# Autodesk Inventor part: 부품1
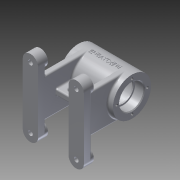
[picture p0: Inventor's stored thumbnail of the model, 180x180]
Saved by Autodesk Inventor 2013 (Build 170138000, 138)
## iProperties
Created: 2015-11
Part Number: 부품1
Material: 알루미늄 6061
Document SubType Name: Modeling
Designer: default
Density: 2.40731 g/cm^3
Mass: 318.572 g
Surface Area: 460.303 cm^2
Volume: 132.335 cm^3
Author: default
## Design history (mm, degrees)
sketch "스케치1"
  geometry: C1 r 25 at (0, 0); 1 further point
  constraints: 1 centre point, 1 coincident
  dimensions: "d0" = 50 diameter of C1
extrude "돌출1" new body sketch "스케치1" distance "d2" = 70; taper "d3" = 0 deg
node "작업 평면1"
sketch "스케치2"
  geometry: L1 (0, 25)-(70, 25) reference; L2 (70, -25)-(70, 25) reference; L3 (0, 25)-(0, -25) reference; L4 (0, -25)-(70, -25) reference; L5 (15, -6.491)-(55, -6.491); L6 (55, -6.491)-(55, -45); L7 (55, -45)-(15, -45); L8 (15, -45)-(15, -6.491); 3 further points
  constraints: 8 end point, 2 midpoint, 2 parallel, 1 horizontal, 1 perpendicular, 1 vertical alignment
  dimensions: "d5" = 20 distance between parallel lines of L4 L7; "d6" = 40 distance of L5.start L5.end
extrude "돌출2" join sketch "스케치2" stored distance "d7" = 8; taper "d8" = 0 deg
sketch "스케치3"
  geometry: L1 (-21, 45)-(29, 45); L2 (29, 45)-(29, -23); L3 (29, -23)-(-21, -23); L4 (-21, -23)-(-21, 45); C1 r 25 at (4, 45) reference; A1 r 25 centre (4, 45) between (0, 20.322) and (8, 20.322) reference; 1 further point
  constraints: 8 end point, 2 midpoint, 2 parallel, 1 coincident, 1 horizontal, 1 perpendicular
  dimensions: "d9" = 68 distance from line of A1.centre L3; "d10" = 50 distance of L1.start L1.end
extrude "돌출3" join sketch "스케치3" distance "d11" = 8; taper "d12" = 0 deg
sketch "스케치4"
  geometry: L1 (0, 0)-(0, 50) reference; L2 (8, 50)-(8, 0) reference; L3 (0, 50)-(8, 50) reference; L4 (20, -15)-(20, 65); L5 (0, 65)-(0, -15); A1 r 10 centre (10, 65) between (20, 65) and (0, 65); A2 r 10 centre (10, -15) between (0, -15) and (20, -15); 4 further points
  constraints: 4 end point, 4 midpoint, 4 point on circle, 4 tangent, 2 centre point, 1 horizontal alignment, 1 parallel, 1 perpendicular
  dimensions: "d13" = 20 distance between parallel lines of L5 L4; "d15" = 80 distance of A2.centre A1.centre
extrude "돌출4" join sketch "스케치4" distance "d16" = 10; taper "d17" = 0 deg
sketch "스케치5"
  geometry: C1 r 10 at (10, 15); C2 r 10 at (10, -65); A1 r 10 centre (10, -65) between (0, -65) and (20, -65) reference; A2 r 10 centre (10, 15) between (20, 15) and (0, 15) reference; 1 further point
  constraints: 2 centre point, 2 coincident, 2 concentric
extrude "돌출5" join sketch "스케치5" distance "d18" = 3; taper "d19" = 0 deg
sketch "스케치6"
  geometry: C1 r 10 at (0, 0) reference; C2 r 10 at (0, 80) reference; 3 further points
  constraints: 2 coincident
hole "구멍1" sketch "스케치6" at (0, 80), (0, 0) diameter "d20" = 6; stored, may be unused: countersink angle "d24" = 90 deg, drill point angle "d26" = 118 deg; dims "d21" = 6, "d22" = 12, "d23" = 4, "d25" = 8
node "작업 평면2"
sketch "스케치7"
  geometry: L1 (-55, -24.678)-(-15, -24.678) reference; L2 (-15, -45)-(-15, -24.678) reference; L3 (-27, -31.5)-(-43, -31.5); L4 (-43, -38.5)-(-27, -38.5); L5 (5, -68)-(-15, -68) reference; A1 r 3.5 centre (-43, -35) between (-43, -31.5) and (-43, -38.5); A2 r 3.5 centre (-27, -35) between (-27, -38.5) and (-27, -31.5); 3 further points
  constraints: 4 end point, 4 point on circle, 4 tangent, 2 centre point, 2 midpoint, 1 parallel, 1 perpendicular, 1 vertical alignment
  dimensions: "d27" = 3.5 radius of A1; "d29" = 16 distance of A2.centre A1.centre; "d30" = 33 distance from line of L5 A2.centre
extrude "돌출6" cut sketch "스케치7" stored distance "d31" = 3; taper "d32" = 0 deg
node "작업 평면3"
sketch "스케치8"
  geometry: L1 (0, 25)-(-70, 25) reference; L2 (0, -25)-(0, 25) reference; C1 r 5 at (-35, 0); 3 further points
  constraints: 2 midpoint, 1 centre point, 1 horizontal alignment, 1 vertical alignment
  dimensions: "d34" = 10 diameter of C1
extrude "돌출7" join sketch "스케치8" distance "d36" = 28; taper "d37" = 0 deg
sketch "스케치9"
  geometry: L1 (0, 0)-(0, -21.987); L2 (0, 0)-(14, -24.249); L3 (19.196, -21.249)-(6.746, 0.316); L4 (14, -24.249)-(19.196, -21.249); L5 (6.746, 0.316)-(1.808, -3.131); C1 r 25 at (0, 0) reference; 1 further point
  constraints: 10 end point, 1 parallel, 1 perpendicular, 1 point on line, 1 vertical
  dimensions: "d38" = 30 deg angle of L2 L1; "d39" = 6 distance between parallel lines of L3 L2; "d41" = 28 distance from line of L4 point (0, 0)
revolve "회전1" sketch "스케치9" stored, may be unused: angle "d42" = 90 deg
sketch "스케치10"
  geometry: C1 r 25 at (0, 0) reference; C2 r 16 at (0, 0)
  constraints: 1 centre point, 1 coincident
  dimensions: "d43" = 32 diameter of C2
extrude "돌출8" cut sketch "스케치10" distance "d45" = 12; taper "d46" = 0 deg
sketch "스케치11"
  geometry: C1 r 16 at (0, 0) reference; C2 r 14 at (0, 0)
  constraints: 1 centre point, 1 coincident
  dimensions: "d47" = 28 diameter of C2
extrude "돌출9" cut sketch "스케치11" distance "d49" = 2; taper "d50" = 0 deg
sketch "스케치12"
  geometry: C1 r 25 at (0, 0) reference; C2 r 16 at (0, 0)
  constraints: 1 centre point, 1 coincident
  dimensions: "d51" = 32 diameter of C2
extrude "돌출10" cut sketch "스케치12" distance "d53" = 12; taper "d54" = 0 deg
sketch "스케치13"
  geometry: C1 r 16 at (0, 0) reference; C2 r 14 at (0, 0)
  constraints: 1 centre point, 1 coincident
  dimensions: "d55" = 28 diameter of C2
extrude "돌출11" cut sketch "스케치13" distance "d57" = 2; taper "d58" = 0 deg
sketch "스케치14"
  geometry: C1 r 14 at (0, 0) reference; C2 r 21 at (0, 0)
  constraints: 1 centre point, 1 coincident
  dimensions: "d59" = 42 diameter of C2
extrude "돌출12" cut sketch "스케치14" distance "d61" = 42; taper "d62" = 0 deg
sketch "스케치15"
  geometry: C1 r 5 at (0, 0) reference; 2 further points
  constraints: 1 coincident
hole "구멍2" sketch "스케치15" at (0, 0) diameter "d63" = 5.188; stored, may be unused: countersink angle "d67" = 90 deg, drill point angle "d69" = 118 deg; dims "d64" = 20, "d65" = 19.05, "d66" = 4.775, "d68" = 20
sketch "스케치16"
  geometry: C1 r 6 at (0, 0) reference; 2 further points
  constraints: 1 coincident
hole "구멍3" sketch "스케치16" at (0, 0) diameter "d70" = 5.188; stored, may be unused: countersink angle "d74" = 90 deg, drill point angle "d76" = 118 deg; dims "d71" = 20, "d72" = 19.05, "d73" = 4.775, "d75" = 20
sketch "스케치17" dims "d77" = 40
  geometry: L1 (0, 0)-(0, 20); C1 r 25 at (0, 0) reference; 1 further point
  constraints: 2 coincident, 2 end point, 1 vertical, 1 vertical alignment, 2 other
hole "구멍4" sketch "스케치17" at (0, 20) diameter "d79" = 3.242; stored, may be unused: countersink angle "d83" = 90 deg, drill point angle "d85" = 118 deg; dims "d80" = 8, "d81" = 19.05, "d82" = 4.775, "d84" = 10
node "작업 평면4"
sketch "스케치18"
  geometry: L1 (0, 25)-(0, -25) reference; L2 (0, 25)-(70, 25) reference; 2 further points
  constraints: 1 other
  dimensions: "d89" = 35 distance from line of point (35, 0) L1; "d90" = 25 distance from line of L2 point (35, 0)
feature "엠보싱1" sketch "스케치18" dims "d91" = 0.5, "d92" = 0
fillet "모깎기1" dims "d93" = 0.3
fillet "모깎기2" dims "d94" = 0.3
fillet "모깎기3" dims "d95" = 3
fillet "모깎기4" dims "d96" = 2
fillet "모깎기5" dims "d97" = 2
fillet "모깎기6" dims "d98" = 2
fillet "모깎기7" dims "d99" = 2
fillet "모깎기8" dims "d100" = 2
fillet "모깎기9" dims "d101" = 2
fillet "모깎기10" dims "d102" = 2
fillet "모깎기11" dims "d103" = 2
chamfer "모따기1" distance "d104" = 1; stored, may be unused: second distance "d105" = 2, angle "d106" = 45 deg
chamfer "모따기2" distance "d107" = 1; stored, may be unused: second distance "d108" = 2, angle "d109" = 45 deg
fillet "모깎기12" dims "d110" = 2
node "솔리드1"
mirror "대칭1"
pattern_circular "원형 패턴1" dims angle "d87" = 360 deg
mirror "대칭2"
node "투영된 루프1"
node "투영된 루프2"
node "투영된 루프3"
other parameters: "d4" = 0, "d33" = 0
